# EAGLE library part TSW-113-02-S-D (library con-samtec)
THROUGH-HOLE .025" SQ POST HEADER Source: Samtec TSW.pdf
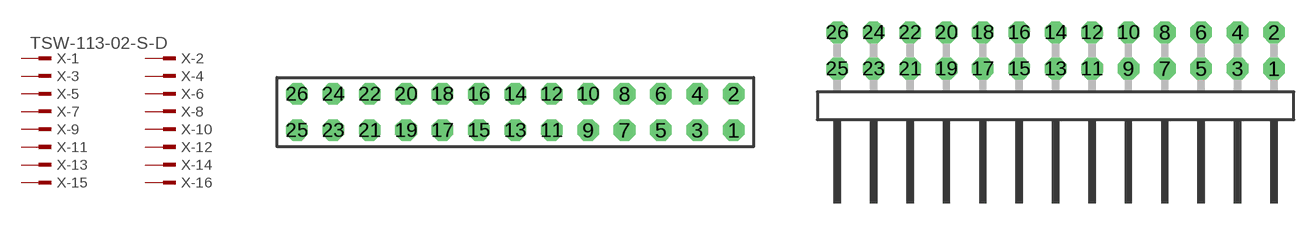
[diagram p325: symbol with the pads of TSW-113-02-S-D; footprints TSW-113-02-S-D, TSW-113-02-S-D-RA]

Designator prefix X; gates -1=MPINV -2=MPIN -3=MPIN -4=MPIN -5=MPIN -6=MPIN -7=MPIN -8=MPIN -9=MPIN -10=MPIN -11=MPIN -12=MPIN -13=MPIN -14=MPIN -15=MPIN -16=MPIN -17=MPIN -18=MPIN -19=MPIN -20=MPIN -21=MPIN -22=MPIN -23=MPIN -24=MPIN -25=MPIN -26=MPIN

## TSW-113-02-S-D (OC_FARNELL: unknown; OC_NEWARK: unknown)  [TSW-113-02-S-D]
1  -1:1  pas
2  -2:1  pas
3  -3:1  pas
4  -4:1  pas
5  -5:1  pas
6  -6:1  pas
7  -7:1  pas
8  -8:1  pas
9  -9:1  pas
10  -10:1  pas
11  -11:1  pas
12  -12:1  pas
13  -13:1  pas
14  -14:1  pas
15  -15:1  pas
16  -16:1  pas
17  -17:1  pas
18  -18:1  pas
19  -19:1  pas
20  -20:1  pas
21  -21:1  pas
22  -22:1  pas
23  -23:1  pas
24  -24:1  pas
25  -25:1  pas
26  -26:1  pas

## TSW-113-02-S-D-RA (OC_FARNELL: unknown; OC_NEWARK: unknown)  [TSW-113-02-S-D-RA]
Pads as for TSW-113-02-S-D

## Footprint TSW-113-02-S-D (pad centres in mm)
THROUGH-HOLE .025" SQ POST HEADER Source: Samtec TSW.pdf
drill 1 pad 1.5 octagon: 1 15.24,-1.27; 2 15.24,1.27; 3 12.7,-1.27; 4 12.7,1.27; 5 10.16,-1.27; 6 10.16,1.27; 7 7.62,-1.27; 8 7.62,1.27; 9 5.08,-1.27; 10 5.08,1.27; 11 2.54,-1.27; 12 2.54,1.27; 13 0,-1.27; 14 0,1.27; 15 -2.54,-1.27; 16 -2.54,1.27; 17 -5.08,-1.27; 18 -5.08,1.27; 19 -7.62,-1.27; 20 -7.62,1.27; 21 -10.16,-1.27; 22 -10.16,1.27; 23 -12.7,-1.27; 24 -12.7,1.27; 25 -15.24,-1.27; 26 -15.24,1.27

## Footprint TSW-113-02-S-D-RA (pad centres in mm)
THROUGH-HOLE .025" SQ POST HEADER Source: Samtec TSW.pdf
drill 1 pad 1.5 octagon: 1 15.24,1.524; 2 15.24,4.064; 3 12.7,1.524; 4 12.7,4.064; 5 10.16,1.524; 6 10.16,4.064; 7 7.62,1.524; 8 7.62,4.064; 9 5.08,1.524; 10 5.08,4.064; 11 2.54,1.524; 12 2.54,4.064; 13 0,1.524; 14 0,4.064; 15 -2.54,1.524; 16 -2.54,4.064; 17 -5.08,1.524; 18 -5.08,4.064; 19 -7.62,1.524; 20 -7.62,4.064; 21 -10.16,1.524; 22 -10.16,4.064; 23 -12.7,1.524; 24 -12.7,4.064; 25 -15.24,1.524; 26 -15.24,4.064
